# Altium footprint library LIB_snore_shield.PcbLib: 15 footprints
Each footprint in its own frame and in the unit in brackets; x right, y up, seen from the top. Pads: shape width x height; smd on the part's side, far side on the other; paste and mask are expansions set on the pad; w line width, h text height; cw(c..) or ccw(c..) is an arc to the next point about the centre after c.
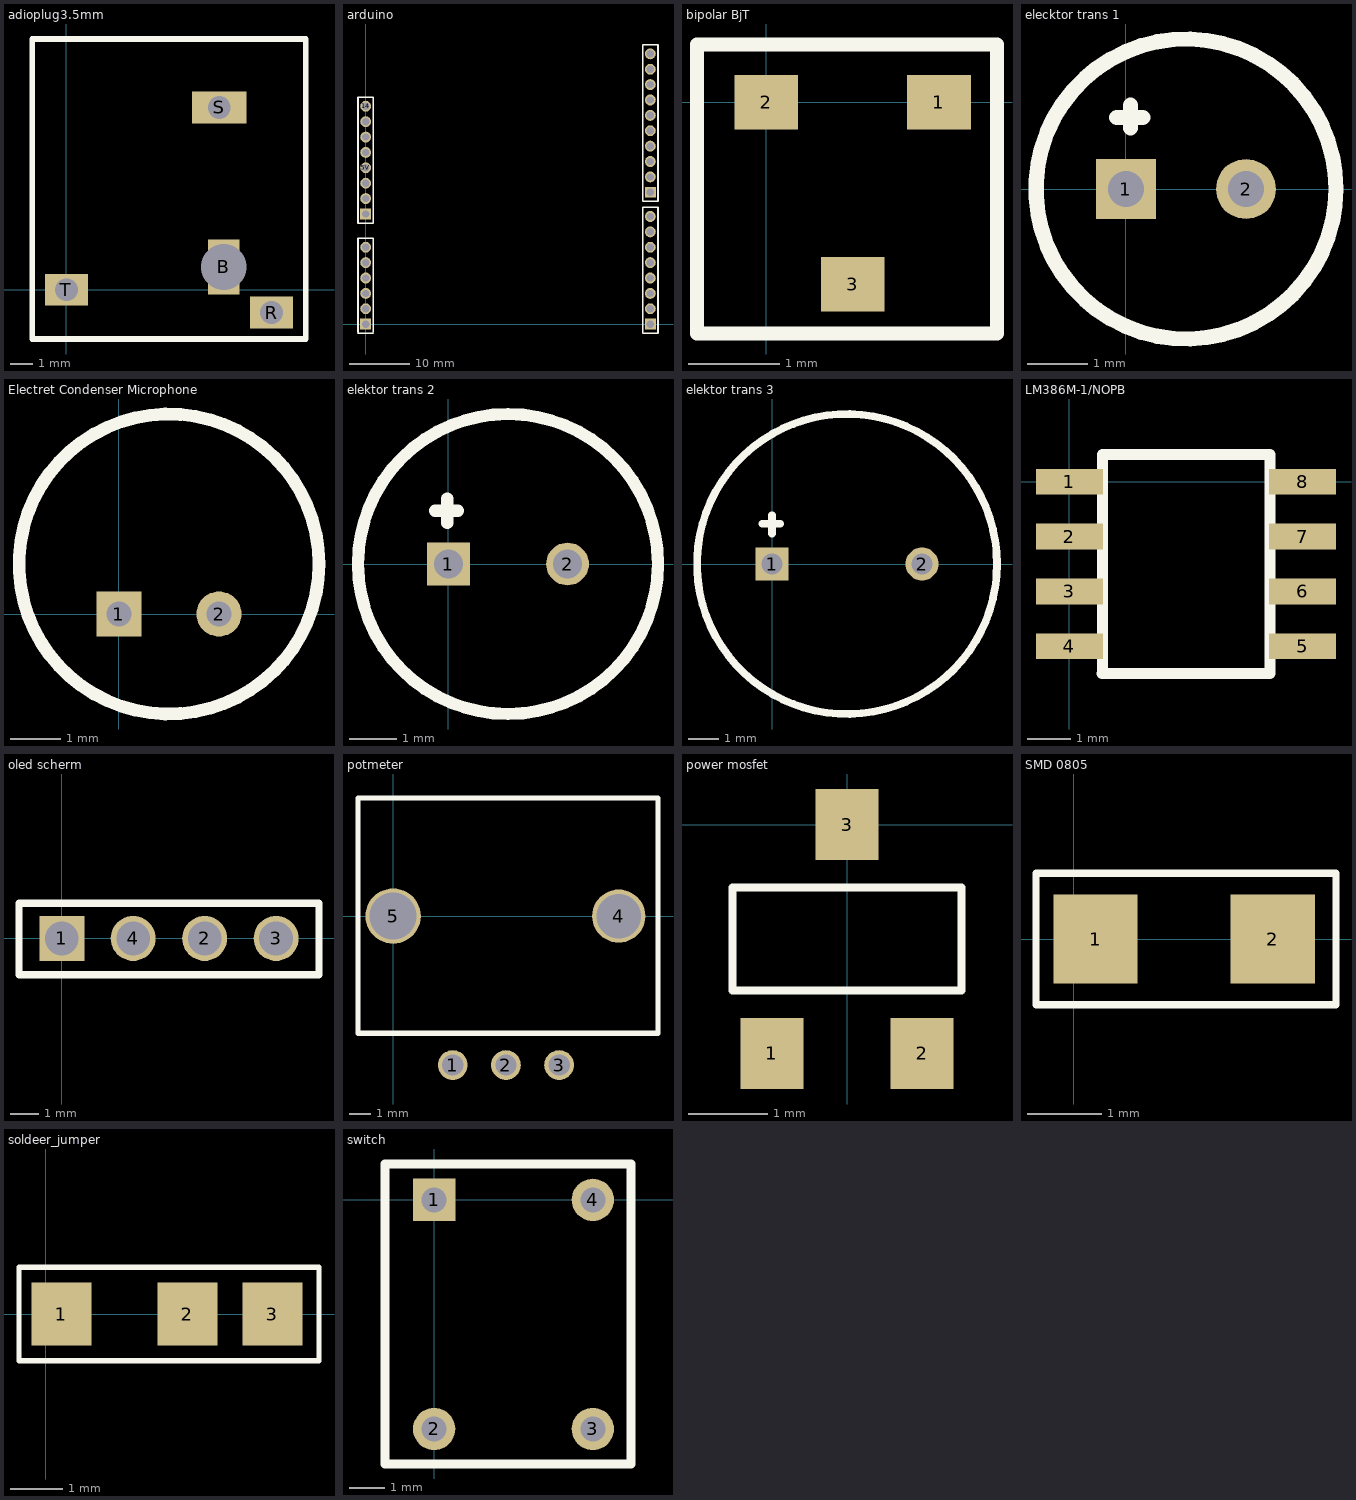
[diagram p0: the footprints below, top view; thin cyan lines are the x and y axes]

## adioplug3.5mm [mm]
pads (4):
  rect 1.4x2.4 hole 2 square: B(6.9,1)
  rect 1.9x1.4 hole 1 square: R(9,-1)
  rect 2.4x1.4 / inner rect 2.2x1.27 / far side rect 2.2x1.2 hole 1 square: S(6.7,8)
  rect 1.9x1.4 / inner rect 2.54x1.27 / far side rect 1.7x1.2 hole 1 square: T(0,0)
Top Overlay:
  lines w0.254: -1.5,-2.159 -1.5,11 10.5,11 10.5,-2.159 -1.5,-2.159

## arduino [mm]
pads (32):
  round 1.8 hole 1.2: 3.3V(0,28.36) 5V(0,25.82) 14(0,35.98) A0/PC0(0,12.7) A1/PC1(0,10.16) A2/PC2(0,7.62) A3/PC3(0,5.08) A4/PC4(0,2.54) A4/PC4(47,42.1) A5/PC5(47,44.64) AREF(47,39.56) GND(0,20.74) GND(0,23.28) GND(47,37.02) INT0/PD2(47,5.08) INT1/PD3(47,7.62) IOREF(0,33.44) MISO/PB4(47,31.94) MOSI/PB3(47,29.4) PB1(47,24.32) PD4(47,10.16) PD5(47,12.7) PD6(47,15.24) PD7(47,17.78) RST/PC6(0,30.9) SCK/PB5(47,34.48) SS/PB2(47,26.86) TX/PD1(47,2.54)
  rect 1.8x1.8 hole 1.2: A5/PC5(0,0) PB0(47,21.78) RX/PD0(47,0) VIN(0,18.2)
Top Overlay:
  lines w0.254: -1.27,-1.52 1.27,-1.52 ; -1.27,-1.372 -1.27,14.22 1.27,14.22 1.27,-1.372 ; -1.27,16.68 -1.27,37.5 1.27,37.5 1.27,16.68 -1.27,16.68 ; 45.73,-1.52 45.73,19.3 48.27,19.3 48.27,-1.52 45.73,-1.52 ; 45.73,20.26 45.73,46.16 48.27,46.16 48.27,20.26 45.73,20.26

## bipolar BjT [mm]
pads (3):
  rect 0.7x0.6 smd: 1(1.9,0) 2(0,0) 3(0.95,-2)
Top Overlay:
  lines w0.154: -0.762,-2.54 -0.762,0.635 2.538,0.635 2.538,-2.54 -0.762,-2.54

## elecktor trans 1 [mm]
pads (2):
  rect 1x1 hole 0.6: 1(0,0)
  round 1 hole 0.6: 2(2,0)
Top Overlay:
  circle w0.254: c1,0 r2.5
  lines w0.254: -0.152,1.194 0.279,1.194 ; 0.076,1.016 0.076,1.397

## Electret Condenser Microphone [mm]
pads (2):
  rect 0.9x0.9 hole 0.5: 1(0,0)
  round 0.9 hole 0.5: 2(2,0)
Top Overlay:
  circle w0.254: c1,1 r3

## elektor trans 2 [mm]
pads (2):
  rect 0.9x0.9 hole 0.6: 1(0,0)
  round 0.9 hole 0.6: 2(2.5,0)
Top Overlay:
  circle w0.254: c1.25,0 r3.15
  lines w0.254: -0.279,1.118 0.203,1.118 ; -0.025,0.864 -0.025,1.372

## elektor trans 3 [mm]
pads (2):
  rect 1.1x1.1 hole 0.7: 1(0,0)
  round 1.1 hole 0.7: 2(5,0)
Top Overlay:
  circle w0.254: c2.5,0 r5
  lines w0.254: -0.33,1.346 0.279,1.346 ; 0,1.016 0,1.626

## LM386M-1/NOPB [mm]
pads (8):
  rect 1.55x0.6 smd: 1(0,0) 2(0,-1.27) 3(0,-2.54) 4(0,-3.81) 5(5.4,-3.81) 6(5.4,-2.54) 7(5.4,-1.27) 8(5.4,0)
Top Overlay:
  lines w0.254: 0.75,-4.445 4.65,-4.445 4.65,0.635 0.762,0.635 0.762,-0.635 0.762,-3.175 0.762,-4.445

## oled scherm [mm]
pads (4):
  rect 1.6x1.6 hole 1.2: 1(0,0)
  round 1.6 hole 1.2: 2(5.08,0) 3(7.62,0) 4(2.54,0)
Top Overlay:
  lines w0.254: -1.52,-1.29 9.144,-1.29 9.144,1.25 -1.52,1.25 -1.52,-1.29

## PCBComponent_1 [mm]

## potmeter [mm]
pads (5):
  round 1.4 hole 1: 1(2.8,-7) 2(5.3,-7)
  round 1.4 / inner oval 1.4x0.064 / far side round 1.4 hole 1: 3(7.8,-7)
  round 2.5 / inner oval 2.5x0.064 / far side round 2.5 hole 2.1: 4(10.6,0)
  round 2.6 / inner round 2.5 / far side round 2.5 hole 2.2: 5(0,0)
Top Overlay:
  lines w0.254: -1.651,-5.5 -1.651,5.549 12.446,5.549 12.446,-5.5 -1.651,-5.5

## power mosfet [mm]
pads (3):
  rect 0.8x0.9 smd: 1(-0.95,-2.9) 2(0.95,-2.9) 3(0,0)
Top Overlay:
  lines w0.1: -1.45,-2.1 1.45,-2.1 1.45,-0.8 -1.45,-0.8 -1.45,-2.1

## SMD 0805 [mm]
pads (2):
  rect 1.14x1.2 smd: 1(0.3,0) 2(2.7,0)
Top Overlay:
  lines w0.1: -0.508,-0.889 0.035,-0.889 0.797,-0.889 2.251,-0.889 2.667,-0.889 3.556,-0.889 3.556,0.889 -0.508,0.889 -0.508,-0.889

## soldeer_jumper [mm]
pads (3):
  rect 1.14x1.2 smd: 1(0.3,0) 2(2.7,0) 3(4.318,0)
Top Overlay:
  lines w0.1: -0.508,-0.889 5.207,-0.889 5.207,0.889 -0.508,0.889 -0.508,-0.889

## switch [mm]
pads (4):
  rect 1.2x1.2 hole 0.71: 1(0,0)
  round 1.2 hole 0.71: 2(0,-6.5) 3(4.5,-6.5) 4(4.5,0)
Top Overlay:
  lines w0.254: -1.397,-7.493 -1.397,1.016 5.588,1.016 5.588,-7.493 -1.397,-7.493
